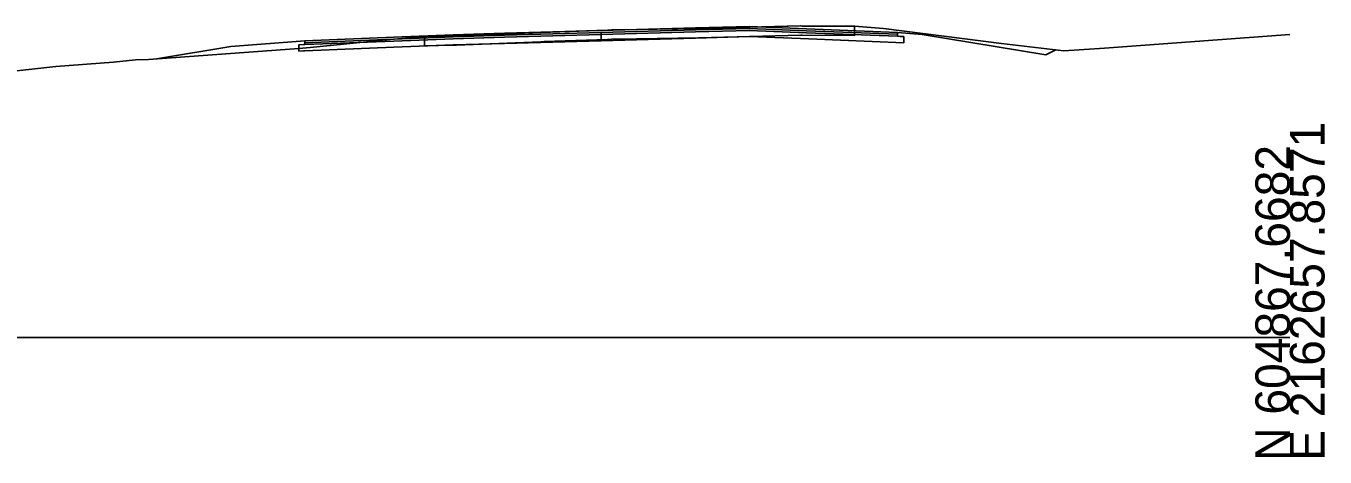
# Model space of a CAD drawing. Extents: x -26 to 1303, y -10 to 12038.
# Drawn here: x 197.6 to 302.8, y 11490.3 to 11525.3 of the extents above; entities that cross this region are included whole.
import ezdxf

# ---------------------------------------------------------------- set-up
doc = ezdxf.new("R2010")
doc.units = 0
for name, color, linetype in [('RD_GPK_XS_Cell', 7, 'Continuous'), ('RD_XS_Base', 7, 'Continuous'), ('RD_XS_ExGround', 7, 'Continuous'), ('RD_XS_ExPaveRet', 7, 'Continuous'), ('RD_XS_Greenside', 7, 'Continuous'), ('RD_XS_Pave', 7, 'Continuous'), ('RD_XS_PaveOvlay_CP', 7, 'Continuous'), ('RD_XS_TieSlope', 7, 'Continuous')]:
    doc.layers.add(name, color=color, linetype=linetype)

msp = doc.modelspace()

# ---------------------------------------------------------------- linework, layer by layer
at = {"layer": 'RD_GPK_XS_Cell'}
msp.add_line((150, 11500), (300, 11500), dxfattribs=at)
at = {"layer": 'RD_XS_Base'}
for p, q in [((251.86, 11524.77), (244.22, 11524.56)), ((244.22, 11524.66), (244.22, 11524.72)), ((244.22, 11524.72), (244.22, 11524.49)), ((244.22, 11524.56), (244.22, 11524.66)), ((256.22, 11524.9), (251.86, 11524.77)), ((260.83, 11524.71), (256.22, 11524.9)), ((268.22, 11524.42), (260.83, 11524.71)), ((220.09, 11523.74), (219.72, 11523.72)), ((219.72, 11523.72), (219.72, 11523.59)), ((219.72, 11523.59), (219.72, 11523.22)), ((220.22, 11523.74), (220.09, 11523.74)), ((227.42, 11524.03), (220.22, 11523.74)), ((232.22, 11524.22), (227.42, 11524.03)), ((227.42, 11523.53), (232.22, 11523.72)), ((236.39, 11524.34), (232.22, 11524.22)), ((232.22, 11523.72), (236.39, 11523.84)), ((244.22, 11524.56), (236.39, 11524.34)), ((236.39, 11523.84), (244.22, 11524.06)), ((244.22, 11524.56), (244.22, 11524.56)), ((244.22, 11524.56), (244.22, 11524.56)), ((244.22, 11524.39), (244.22, 11524.56)), ((244.22, 11524.49), (244.22, 11524.06)), ((244.22, 11524.06), (244.22, 11524.39)), ((244.22, 11524.06), (251.86, 11524.27)), ((251.86, 11524.27), (256.22, 11524.4)), ((256.22, 11524.4), (261.03, 11524.2)), ((261.03, 11524.2), (268.72, 11523.9)), ((268.42, 11524.41), (268.22, 11524.42)), ((268.72, 11524.4), (268.42, 11524.41)), ((268.72, 11524.19), (268.72, 11524.4)), ((268.72, 11523.9), (268.72, 11524.19)), ((219.72, 11523.22), (220.09, 11523.24)), ((220.09, 11523.24), (220.22, 11523.24)), ((220.22, 11523.24), (227.42, 11523.53))]:
    msp.add_line(p, q, dxfattribs=at)
at = {"layer": 'RD_XS_ExGround'}
msp.add_lwpolyline([(195.88, 11521.51), (198.34, 11521.77), (200.05, 11521.96), (204.7, 11522.32), (206.48, 11522.5), (207.54, 11522.53), (219.71, 11523.43), (220.64, 11523.5), (226.83, 11524.12), (229.9, 11524.39), (231.97, 11524.44), (239.32, 11524.73), (244.73, 11524.92), (245.08, 11524.94), (247.06, 11524.97), (251.96, 11525.04), (260.34, 11525.26), (264.73, 11525.24), (267.09, 11525.04), (276.63, 11523.82), (281.69, 11523.24), (284.97, 11523.46), (300, 11524.55)], dxfattribs=at)
at = {"layer": 'RD_XS_ExPaveRet'}
for points in [[(245.08, 11524.94), (244.74, 11524.92), (244.73, 11524.92), (239.6, 11524.74), (239.32, 11524.73), (232.49, 11524.46), (231.97, 11524.44), (230.08, 11524.4), (229.9, 11524.39), (229.9, 11523.72), (229.9, 11523.64), (230.08, 11523.65), (231.97, 11523.69), (232.49, 11523.71), (239.32, 11523.98), (239.6, 11523.99), (244.73, 11524.17), (244.74, 11524.17), (245.08, 11524.19), (245.08, 11524.19), (247.07, 11524.22), (247.08, 11524.22), (252.08, 11524.3), (252.12, 11524.3), (260.39, 11524.51), (260.5, 11524.5), (264.73, 11524.49), (264.73, 11524.49), (264.73, 11524.49), (264.73, 11525.22), (264.73, 11525.24), (264.73, 11525.24), (264.73, 11525.24), (260.5, 11525.25), (260.39, 11525.26), (252.12, 11525.05), (252.08, 11525.05), (247.08, 11524.97), (247.07, 11524.97), (245.08, 11524.94), (245.08, 11524.94)], [(245.08, 11524.94), (244.74, 11524.92), (244.73, 11524.92), (239.6, 11524.74), (239.32, 11524.73), (232.49, 11524.46), (231.97, 11524.44), (230.08, 11524.4), (229.9, 11524.39), (229.9, 11523.72), (229.9, 11523.64), (230.08, 11523.65), (231.97, 11523.69), (232.49, 11523.71), (239.32, 11523.98), (239.6, 11523.99), (244.73, 11524.17), (244.74, 11524.17), (245.08, 11524.19), (245.08, 11524.19), (247.07, 11524.22), (247.08, 11524.22), (252.08, 11524.3), (252.12, 11524.3), (260.39, 11524.51), (260.5, 11524.5), (264.73, 11524.49), (264.73, 11524.49), (264.73, 11525.22), (264.73, 11525.24), (264.73, 11525.24), (260.5, 11525.25), (260.39, 11525.26), (252.12, 11525.05), (252.08, 11525.05), (247.08, 11524.97), (247.07, 11524.97), (245.08, 11524.94), (245.08, 11524.94)]]:
    msp.add_lwpolyline(points, dxfattribs=at)
at = {"layer": 'RD_XS_Greenside'}
for p, q in [((214.22, 11523.58), (208.2, 11522.58)), ((270.22, 11524.57), (280.22, 11522.91)), ((280.22, 11522.91), (281.03, 11523.31))]:
    msp.add_line(p, q, dxfattribs=at)
at = {"layer": 'RD_XS_Pave'}
for p, q in [((236.39, 11524.66), (232.22, 11524.54)), ((244.22, 11524.88), (236.39, 11524.66)), ((244.22, 11524.72), (236.39, 11524.5)), ((236.39, 11524.5), (244.22, 11524.72)), ((251.86, 11525.09), (244.22, 11524.88)), ((251.86, 11524.93), (244.22, 11524.72)), ((244.22, 11524.72), (251.86, 11524.93)), ((244.22, 11524.56), (251.86, 11524.77)), ((244.22, 11524.66), (244.22, 11524.72)), ((244.22, 11524.72), (244.22, 11524.72)), ((244.22, 11524.72), (244.22, 11524.72)), ((244.22, 11524.72), (244.22, 11524.66)), ((244.22, 11524.56), (244.22, 11524.66)), ((244.22, 11524.66), (244.22, 11524.56)), ((256.22, 11525.21), (251.86, 11525.09)), ((256.22, 11525.06), (251.86, 11524.93)), ((251.86, 11524.93), (256.22, 11525.06)), ((251.86, 11524.77), (256.22, 11524.9)), ((260.83, 11525.03), (256.22, 11525.21)), ((260.83, 11524.87), (256.22, 11525.06)), ((256.22, 11525.06), (260.83, 11524.87)), ((256.22, 11524.9), (260.83, 11524.71)), ((268.22, 11524.73), (260.83, 11525.03)), ((268.22, 11524.58), (260.83, 11524.87)), ((260.83, 11524.87), (268.22, 11524.58)), ((260.83, 11524.71), (268.22, 11524.42)), ((268.22, 11524.67), (268.22, 11524.73)), ((268.22, 11524.58), (268.22, 11524.67)), ((227.42, 11524.35), (220.22, 11524.06)), ((227.42, 11524.19), (220.22, 11523.9)), ((220.22, 11523.9), (227.42, 11524.19)), ((220.22, 11524.06), (220.22, 11524.02)), ((220.22, 11523.74), (227.42, 11524.03)), ((220.22, 11524.02), (220.22, 11523.9)), ((220.22, 11523.9), (220.22, 11523.86)), ((220.22, 11523.86), (220.22, 11523.74)), ((232.22, 11524.54), (227.42, 11524.35)), ((232.22, 11524.38), (227.42, 11524.19)), ((227.42, 11524.19), (232.22, 11524.38)), ((227.42, 11524.03), (232.22, 11524.22)), ((236.39, 11524.5), (232.22, 11524.38)), ((232.22, 11524.38), (236.39, 11524.5)), ((232.22, 11524.22), (236.39, 11524.34)), ((236.39, 11524.34), (244.22, 11524.56)), ((244.22, 11524.56), (244.22, 11524.56)), ((244.22, 11524.56), (244.22, 11524.56)), ((268.22, 11524.51), (268.22, 11524.58)), ((268.22, 11524.42), (268.22, 11524.51))]:
    msp.add_line(p, q, dxfattribs=at)
at = {"layer": 'RD_XS_PaveOvlay_CP'}
for p, q in [((236.39, 11524.66), (232.22, 11524.54)), ((244.22, 11524.88), (236.39, 11524.66)), ((251.86, 11525.09), (244.22, 11524.88)), ((256.22, 11525.21), (251.86, 11525.09)), ((260.83, 11525.03), (256.22, 11525.21)), ((268.22, 11524.73), (260.83, 11525.03)), ((227.42, 11524.35), (220.22, 11524.06)), ((232.22, 11524.54), (227.42, 11524.35))]:
    msp.add_line(p, q, dxfattribs=at)
at = {"layer": 'RD_XS_TieSlope'}
for p, q in [((268.22, 11524.73), (270.22, 11524.57)), ((220.22, 11524.06), (214.22, 11523.58))]:
    msp.add_line(p, q, dxfattribs=at)

# ---------------------------------------------------------------- texts
at = {"layer": 'RD_GPK_XS_Cell'}
for s, p in [('E 2162657.8571', (302.8, 11490)), ('N 604867.6682', (300, 11490))]:
    msp.add_text(s, height=2.8, rotation=90, dxfattribs=at).set_placement(p)

doc.saveas('drawing.dxf')
